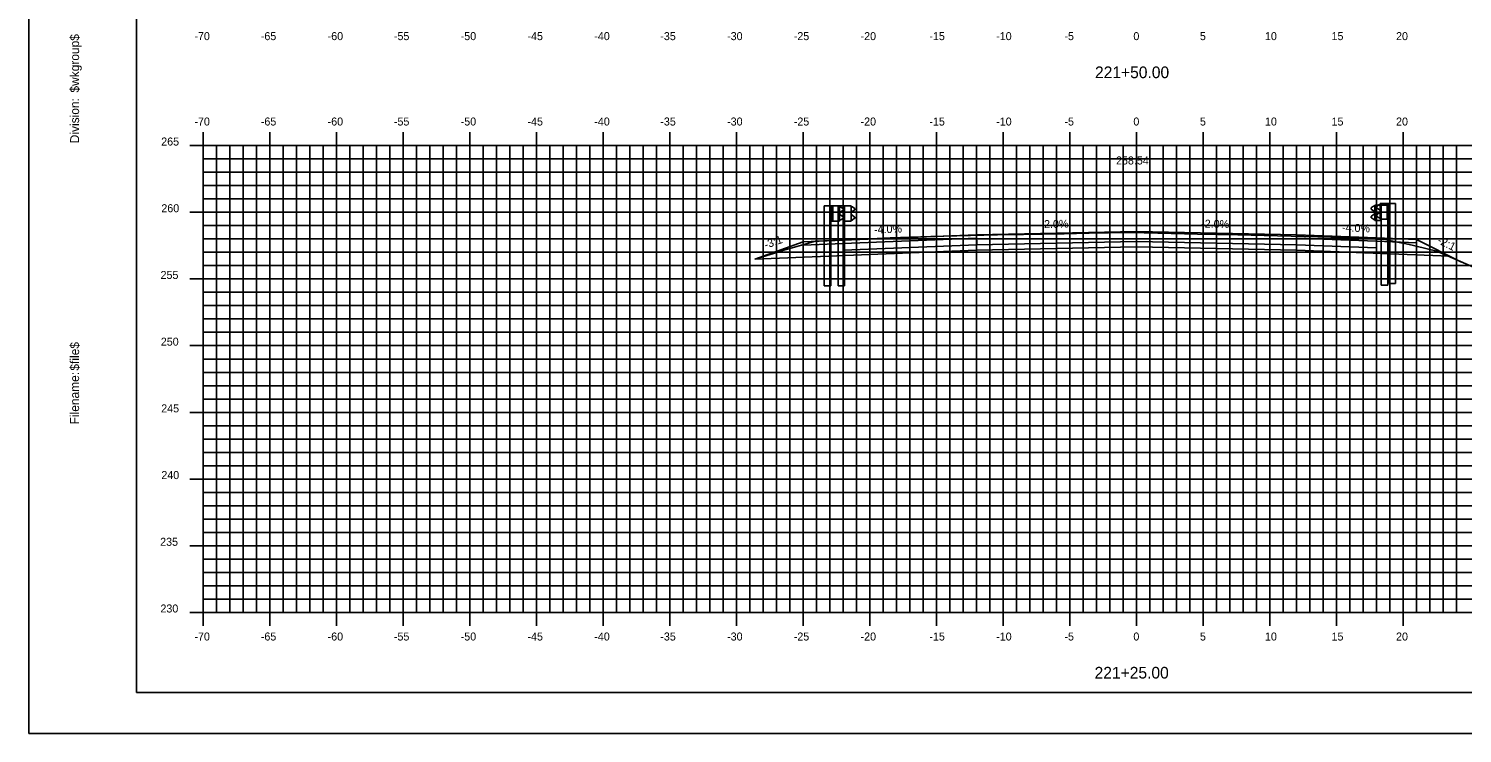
# Model space of a CAD drawing. Extents: x -22 to 1480, y -1511 to 8.
# Drawn here: x 1086.6 to 1194.1, y -184.5 to -131.7 of the extents above; entities that cross this region are included whole.
import ezdxf

# ---------------------------------------------------------------- set-up
doc = ezdxf.new("R2010")
doc.units = 0
for name, color, linetype in [('ANNOTATION', 7, 'Continuous'), ('BORDER', 7, 'Continuous'), ('D_Guardrail_Beam_Lt', 7, 'Continuous'), ('D_Guardrail_Beam_Rt', 7, 'Continuous'), ('D_Roadway_Centerline', 7, 'Continuous'), ('D_Roadway_Centerline_Text', 7, 'Continuous'), ('D_Roadway_Edge_Shoulder', 7, 'Continuous'), ('D_Roadway_Edge_TW', 7, 'Continuous'), ('D_Roadway_SlopeLines', 7, 'Continuous'), ('D_Roadway_SubGrade', 7, 'Continuous'), ('H_V ANNOTATION', 7, 'Continuous'), ('MAJOR', 7, 'Continuous'), ('MINOR', 7, 'Continuous'), ('PLOT BOUNDARY', 7, 'Continuous'), ('S_Guardrail_Beam', 7, 'Continuous'), ('S_Roadway_Centerline', 7, 'Continuous')]:
    doc.layers.add(name, color=color, linetype=linetype)

msp = doc.modelspace()

# ---------------------------------------------------------------- linework, layer by layer
at = {"layer": 'BORDER'}
for p, q in [((1094.72, -76.47), (1094.72, -181.47)), ((1094.72, -181.47), (1254.72, -181.47))]:
    msp.add_line(p, q, dxfattribs=at)
at = {"layer": 'D_Guardrail_Beam_Lt'}
for p, q in [((1187.9, -144.92), (1187.76, -145.02)), ((1187.99, -144.9), (1187.92, -144.92)), ((1187.99, -144.82), (1188.68, -144.82)), ((1187.99, -145.99), (1187.99, -144.82)), ((1188.51, -144.82), (1188.51, -145.99)), ((1188.62, -144.82), (1188.62, -145.99)), ((1188.68, -144.82), (1189.15, -144.82)), ((1188.68, -144.82), (1188.68, -145.99)), ((1189.15, -144.82), (1189.15, -150.82)), ((1187.76, -145.17), (1187.95, -145.3)), ((1187.95, -145.5), (1187.76, -145.64)), ((1187.76, -145.78), (1187.9, -145.88)), ((1187.92, -145.89), (1187.99, -145.9)), ((1187.99, -145.37), (1187.99, -145.44)), ((1188.68, -145.99), (1187.99, -145.99)), ((1188.66, -150.82), (1188.66, -145.99)), ((1188.66, -150.82), (1189.15, -150.82))]:
    msp.add_line(p, q, dxfattribs=at)
for centre, major_axis, start_param, end_param in [((1187.81, -145.09), (-0.0877, 0), 5.323254, 7.243116), ((1187.93, -144.96), (-0.0417, 0), 4.907132, 5.323254), ((1187.81, -145.71), (-0.0877, 0), 5.323254, 7.243116), ((1187.93, -145.85), (-0.0417, 0), 0.959931, 1.376053), ((1187.91, -145.37), (0.0789, 0), 0, 0.959931), ((1187.91, -145.44), (0.0789, 0), 5.323254, 6.283185)]:
    msp.add_ellipse(centre, major_axis=major_axis, ratio=0.995501, start_param=start_param, end_param=end_param, dxfattribs=at)
at = {"layer": 'D_Guardrail_Beam_Rt'}
for p, q in [((1146.29, -144.98), (1146.29, -150.98)), ((1146.76, -144.98), (1146.29, -144.98)), ((1147.45, -144.98), (1146.76, -144.98)), ((1146.76, -144.98), (1146.76, -146.15)), ((1146.83, -144.98), (1146.83, -146.15)), ((1146.93, -144.98), (1146.93, -146.15)), ((1147.45, -146.15), (1147.45, -144.98)), ((1147.45, -145.06), (1147.53, -145.08)), ((1147.54, -145.08), (1147.68, -145.18)), ((1146.76, -146.15), (1147.45, -146.15)), ((1146.78, -150.98), (1146.78, -146.15)), ((1147.53, -146.05), (1147.45, -146.06)), ((1147.46, -145.53), (1147.46, -145.6)), ((1147.68, -145.33), (1147.49, -145.46)), ((1147.49, -145.66), (1147.68, -145.8)), ((1147.68, -145.94), (1147.54, -146.04)), ((1146.78, -150.98), (1146.29, -150.98))]:
    msp.add_line(p, q, dxfattribs=at)
for centre, major_axis, start_param, end_param in [((1147.52, -145.12), (0.0417, 0), 0.959931, 1.376053), ((1147.53, -145.53), (-0.0789, 0), 5.323254, 6.283185), ((1147.53, -145.6), (-0.0789, 0), 6.283185, 7.243116), ((1147.52, -146.01), (0.0417, 0), 4.907132, 5.323254), ((1147.63, -145.25), (0.0877, 0), 5.323254, 7.243116), ((1147.63, -145.87), (0.0877, 0), 5.323254, 7.243116)]:
    msp.add_ellipse(centre, major_axis=major_axis, ratio=0.995501, start_param=start_param, end_param=end_param, dxfattribs=at)
at = {"layer": 'D_Roadway_Centerline'}
msp.add_lwpolyline([(1141.09, -148.98), (1144.72, -147.68), (1147.72, -147.56), (1157.72, -147.16), (1169.72, -146.92), (1181.72, -147.16), (1187.72, -147.4), (1190.72, -147.52), (1194.09, -149.21)], dxfattribs=at)
at = {"layer": 'D_Roadway_Edge_Shoulder'}
for points in [[(1157.72, -147.16), (1147.72, -147.56), (1147.72, -147.56), (1144.72, -147.68), (1144.72, -147.93), (1147.72, -147.81), (1147.72, -147.81), (1157.72, -147.41)], [(1157.72, -147.16), (1147.72, -147.56), (1147.72, -147.56), (1144.72, -147.68), (1144.72, -147.93), (1147.72, -147.81), (1147.72, -147.81), (1147.73, -148.31), (1157.73, -147.91)], [(1181.72, -147.16), (1187.72, -147.4), (1187.72, -147.4), (1190.72, -147.52), (1190.72, -147.77), (1187.72, -147.65), (1187.72, -147.65), (1187.71, -148.15), (1181.71, -147.91)], [(1181.72, -147.16), (1187.72, -147.4), (1187.72, -147.4), (1190.72, -147.52), (1190.72, -147.77), (1187.72, -147.65), (1187.72, -147.65), (1181.72, -147.41)]]:
    msp.add_lwpolyline(points, close=True, dxfattribs=at)
at = {"layer": 'D_Roadway_Edge_TW'}
msp.add_lwpolyline([(1181.72, -147.91), (1181.72, -147.16), (1169.72, -146.92), (1157.72, -147.16), (1157.72, -147.91), (1169.72, -147.67)], close=True, dxfattribs=at)
at = {"layer": 'D_Roadway_SlopeLines'}
for points in [[(1144.72, -147.68), (1141.09, -148.98)], [(1190.72, -147.52), (1194.09, -149.21)]]:
    msp.add_lwpolyline(points, dxfattribs=at)
at = {"layer": 'D_Roadway_SubGrade'}
for p, q in [((1157.72, -148.31), (1141.09, -148.98)), ((1181.72, -148.31), (1193.22, -148.77))]:
    msp.add_line(p, q, dxfattribs=at)
msp.add_lwpolyline([(1181.72, -148.31), (1181.72, -147.91), (1169.72, -147.67), (1157.72, -147.91), (1157.72, -148.31), (1169.72, -148.07)], close=True, dxfattribs=at)
at = {"layer": 'MAJOR'}
for p, q in [((1099.72, -139.46), (1099.72, -140.47)), ((1104.72, -139.46), (1104.72, -140.47)), ((1109.72, -139.46), (1109.72, -140.47)), ((1114.72, -139.46), (1114.72, -140.47)), ((1119.72, -139.46), (1119.72, -140.47)), ((1124.72, -139.46), (1124.72, -140.47)), ((1129.72, -139.46), (1129.72, -140.47)), ((1134.72, -139.46), (1134.72, -140.47)), ((1139.72, -139.46), (1139.72, -140.47)), ((1144.72, -139.46), (1144.72, -140.47)), ((1149.72, -139.46), (1149.72, -140.47)), ((1154.72, -139.46), (1154.72, -140.47)), ((1159.72, -139.46), (1159.72, -140.47)), ((1164.72, -139.46), (1164.72, -140.47)), ((1169.72, -139.46), (1169.72, -140.47)), ((1174.72, -139.46), (1174.72, -140.47)), ((1179.72, -139.46), (1179.72, -140.47)), ((1184.72, -139.46), (1184.72, -140.47)), ((1189.72, -139.46), (1189.72, -140.47)), ((1098.72, -140.47), (1099.72, -140.47)), ((1099.72, -140.47), (1239.72, -140.47)), ((1099.72, -175.47), (1099.72, -140.47)), ((1099.72, -175.47), (1099.72, -140.47)), ((1099.72, -140.47), (1239.72, -140.47)), ((1104.72, -175.47), (1104.72, -140.47)), ((1109.72, -175.47), (1109.72, -140.47)), ((1114.72, -175.47), (1114.72, -140.47)), ((1119.72, -175.47), (1119.72, -140.47)), ((1124.72, -175.47), (1124.72, -140.47)), ((1129.72, -175.47), (1129.72, -140.47)), ((1134.72, -175.47), (1134.72, -140.47)), ((1139.72, -175.47), (1139.72, -140.47)), ((1144.72, -175.47), (1144.72, -140.47)), ((1149.72, -175.47), (1149.72, -140.47)), ((1154.72, -175.47), (1154.72, -140.47)), ((1159.72, -175.47), (1159.72, -140.47)), ((1164.72, -175.47), (1164.72, -140.47)), ((1169.72, -175.47), (1169.72, -140.47)), ((1174.72, -175.47), (1174.72, -140.47)), ((1179.72, -175.47), (1179.72, -140.47)), ((1184.72, -175.47), (1184.72, -140.47)), ((1189.72, -175.47), (1189.72, -140.47)), ((1098.72, -145.47), (1099.72, -145.47)), ((1099.72, -145.47), (1239.72, -145.47)), ((1098.72, -150.47), (1099.72, -150.47)), ((1099.72, -150.47), (1239.72, -150.47)), ((1098.72, -155.47), (1099.72, -155.47)), ((1099.72, -155.47), (1239.72, -155.47)), ((1098.72, -160.47), (1099.72, -160.47)), ((1099.72, -160.47), (1239.72, -160.47)), ((1098.72, -165.47), (1099.72, -165.47)), ((1099.72, -165.47), (1239.72, -165.47)), ((1098.72, -170.47), (1099.72, -170.47)), ((1099.72, -170.47), (1239.72, -170.47)), ((1098.72, -175.47), (1099.72, -175.47)), ((1099.72, -175.47), (1239.72, -175.47)), ((1099.72, -175.47), (1239.72, -175.47)), ((1099.72, -176.47), (1099.72, -175.47)), ((1104.72, -176.47), (1104.72, -175.47)), ((1109.72, -176.47), (1109.72, -175.47)), ((1114.72, -176.47), (1114.72, -175.47)), ((1119.72, -176.47), (1119.72, -175.47)), ((1124.72, -176.47), (1124.72, -175.47)), ((1129.72, -176.47), (1129.72, -175.47)), ((1134.72, -176.47), (1134.72, -175.47)), ((1139.72, -176.47), (1139.72, -175.47)), ((1144.72, -176.47), (1144.72, -175.47)), ((1149.72, -176.47), (1149.72, -175.47)), ((1154.72, -176.47), (1154.72, -175.47)), ((1159.72, -176.47), (1159.72, -175.47)), ((1164.72, -176.47), (1164.72, -175.47)), ((1169.72, -176.47), (1169.72, -175.47)), ((1174.72, -176.47), (1174.72, -175.47)), ((1179.72, -176.47), (1179.72, -175.47)), ((1184.72, -176.47), (1184.72, -175.47)), ((1189.72, -176.47), (1189.72, -175.47))]:
    msp.add_line(p, q, dxfattribs=at)
at = {"layer": 'MINOR'}
for p, q in [((1100.72, -175.47), (1100.72, -140.47)), ((1101.72, -175.47), (1101.72, -140.47)), ((1102.72, -175.47), (1102.72, -140.47)), ((1103.72, -175.47), (1103.72, -140.47)), ((1105.72, -175.47), (1105.72, -140.47)), ((1106.72, -175.47), (1106.72, -140.47)), ((1107.72, -175.47), (1107.72, -140.47)), ((1108.72, -175.47), (1108.72, -140.47)), ((1110.72, -175.47), (1110.72, -140.47)), ((1111.72, -175.47), (1111.72, -140.47)), ((1112.72, -175.47), (1112.72, -140.47)), ((1113.72, -175.47), (1113.72, -140.47)), ((1115.72, -175.47), (1115.72, -140.47)), ((1116.72, -175.47), (1116.72, -140.47)), ((1117.72, -175.47), (1117.72, -140.47)), ((1118.72, -175.47), (1118.72, -140.47)), ((1120.72, -175.47), (1120.72, -140.47)), ((1121.72, -175.47), (1121.72, -140.47)), ((1122.72, -175.47), (1122.72, -140.47)), ((1123.72, -175.47), (1123.72, -140.47)), ((1125.72, -175.47), (1125.72, -140.47)), ((1126.72, -175.47), (1126.72, -140.47)), ((1127.72, -175.47), (1127.72, -140.47)), ((1128.72, -175.47), (1128.72, -140.47)), ((1130.72, -175.47), (1130.72, -140.47)), ((1131.72, -175.47), (1131.72, -140.47)), ((1132.72, -175.47), (1132.72, -140.47)), ((1133.72, -175.47), (1133.72, -140.47)), ((1135.72, -175.47), (1135.72, -140.47)), ((1136.72, -175.47), (1136.72, -140.47)), ((1137.72, -175.47), (1137.72, -140.47)), ((1138.72, -175.47), (1138.72, -140.47)), ((1140.72, -175.47), (1140.72, -140.47)), ((1141.72, -175.47), (1141.72, -140.47)), ((1142.72, -175.47), (1142.72, -140.47)), ((1143.72, -175.47), (1143.72, -140.47)), ((1145.72, -175.47), (1145.72, -140.47)), ((1146.72, -175.47), (1146.72, -140.47)), ((1147.72, -175.47), (1147.72, -140.47)), ((1148.72, -175.47), (1148.72, -140.47)), ((1150.72, -175.47), (1150.72, -140.47)), ((1151.72, -175.47), (1151.72, -140.47)), ((1152.72, -175.47), (1152.72, -140.47)), ((1153.72, -175.47), (1153.72, -140.47)), ((1155.72, -175.47), (1155.72, -140.47)), ((1156.72, -175.47), (1156.72, -140.47)), ((1157.72, -175.47), (1157.72, -140.47)), ((1158.72, -175.47), (1158.72, -140.47)), ((1160.72, -175.47), (1160.72, -140.47)), ((1161.72, -175.47), (1161.72, -140.47)), ((1162.72, -175.47), (1162.72, -140.47)), ((1163.72, -175.47), (1163.72, -140.47)), ((1165.72, -175.47), (1165.72, -140.47)), ((1166.72, -175.47), (1166.72, -140.47)), ((1167.72, -175.47), (1167.72, -140.47)), ((1168.72, -175.47), (1168.72, -140.47)), ((1170.72, -175.47), (1170.72, -140.47)), ((1171.72, -175.47), (1171.72, -140.47)), ((1172.72, -175.47), (1172.72, -140.47)), ((1173.72, -175.47), (1173.72, -140.47)), ((1175.72, -175.47), (1175.72, -140.47)), ((1176.72, -175.47), (1176.72, -140.47)), ((1177.72, -175.47), (1177.72, -140.47)), ((1178.72, -175.47), (1178.72, -140.47)), ((1180.72, -175.47), (1180.72, -140.47)), ((1181.72, -175.47), (1181.72, -140.47)), ((1182.72, -175.47), (1182.72, -140.47)), ((1183.72, -175.47), (1183.72, -140.47)), ((1185.72, -175.47), (1185.72, -140.47)), ((1186.72, -175.47), (1186.72, -140.47)), ((1187.72, -175.47), (1187.72, -140.47)), ((1188.72, -175.47), (1188.72, -140.47)), ((1190.72, -175.47), (1190.72, -140.47)), ((1191.72, -175.47), (1191.72, -140.47)), ((1192.72, -175.47), (1192.72, -140.47)), ((1193.72, -175.47), (1193.72, -140.47)), ((1099.72, -141.47), (1239.72, -141.47)), ((1099.72, -141.47), (1100.72, -141.47)), ((1099.72, -142.47), (1239.72, -142.47)), ((1099.72, -142.47), (1100.72, -142.47)), ((1099.72, -143.47), (1239.72, -143.47)), ((1099.72, -143.47), (1100.72, -143.47)), ((1099.72, -144.47), (1239.72, -144.47)), ((1099.72, -144.47), (1100.72, -144.47)), ((1099.72, -146.47), (1239.72, -146.47)), ((1099.72, -146.47), (1100.72, -146.47)), ((1099.72, -147.47), (1239.72, -147.47)), ((1099.72, -147.47), (1100.72, -147.47)), ((1099.72, -148.47), (1239.72, -148.47)), ((1099.72, -148.47), (1100.72, -148.47)), ((1099.72, -149.47), (1239.72, -149.47)), ((1099.72, -149.47), (1100.72, -149.47)), ((1099.72, -151.47), (1239.72, -151.47)), ((1099.72, -151.47), (1100.72, -151.47)), ((1099.72, -152.47), (1239.72, -152.47)), ((1099.72, -152.47), (1100.72, -152.47)), ((1099.72, -153.47), (1239.72, -153.47)), ((1099.72, -153.47), (1100.72, -153.47)), ((1099.72, -154.47), (1239.72, -154.47)), ((1099.72, -154.47), (1100.72, -154.47)), ((1099.72, -156.47), (1239.72, -156.47)), ((1099.72, -156.47), (1100.72, -156.47)), ((1099.72, -157.47), (1239.72, -157.47)), ((1099.72, -157.47), (1100.72, -157.47)), ((1099.72, -158.47), (1239.72, -158.47)), ((1099.72, -158.47), (1100.72, -158.47)), ((1099.72, -159.47), (1239.72, -159.47)), ((1099.72, -159.47), (1100.72, -159.47)), ((1099.72, -161.47), (1239.72, -161.47)), ((1099.72, -161.47), (1100.72, -161.47)), ((1099.72, -162.47), (1239.72, -162.47)), ((1099.72, -162.47), (1100.72, -162.47)), ((1099.72, -163.47), (1239.72, -163.47)), ((1099.72, -163.47), (1100.72, -163.47)), ((1099.72, -164.47), (1239.72, -164.47)), ((1099.72, -164.47), (1100.72, -164.47)), ((1099.72, -166.47), (1239.72, -166.47)), ((1099.72, -166.47), (1100.72, -166.47)), ((1099.72, -167.47), (1239.72, -167.47)), ((1099.72, -167.47), (1100.72, -167.47)), ((1099.72, -168.47), (1239.72, -168.47)), ((1099.72, -168.47), (1100.72, -168.47)), ((1099.72, -169.47), (1239.72, -169.47)), ((1099.72, -169.47), (1100.72, -169.47)), ((1099.72, -171.47), (1239.72, -171.47)), ((1099.72, -171.47), (1100.72, -171.47)), ((1099.72, -172.47), (1239.72, -172.47)), ((1099.72, -172.47), (1100.72, -172.47)), ((1099.72, -173.47), (1239.72, -173.47)), ((1099.72, -173.47), (1100.72, -173.47)), ((1099.72, -174.47), (1239.72, -174.47)), ((1099.72, -174.47), (1100.72, -174.47))]:
    msp.add_line(p, q, dxfattribs=at)
at = {"layer": 'PLOT BOUNDARY'}
msp.add_lwpolyline([(1086.63, -184.53), (1256.63, -184.53), (1256.63, -74.53), (1086.63, -74.53)], close=True, dxfattribs=at)
at = {"layer": 'S_Guardrail_Beam'}
for p, q in [((1147.33, -144.98), (1147.33, -150.98)), ((1147.82, -144.98), (1147.33, -144.98)), ((1148.31, -144.98), (1147.82, -144.98)), ((1147.82, -144.98), (1147.82, -146.14)), ((1148.31, -146.14), (1148.31, -144.98)), ((1148.31, -145.05), (1148.39, -145.06)), ((1148.41, -145.07), (1148.55, -145.17)), ((1187.48, -145.02), (1187.34, -145.12)), ((1187.58, -145), (1187.5, -145.01)), ((1187.58, -144.93), (1188.07, -144.93)), ((1187.58, -146.09), (1187.58, -144.93)), ((1188.07, -144.93), (1188.56, -144.93)), ((1188.07, -144.93), (1188.07, -146.09)), ((1188.56, -144.93), (1188.56, -150.93)), ((1147.82, -150.98), (1147.82, -146.14)), ((1147.82, -146.14), (1148.31, -146.14)), ((1148.39, -146.06), (1148.31, -146.07)), ((1148.32, -145.51), (1148.32, -145.61)), ((1148.55, -145.31), (1148.36, -145.45)), ((1148.36, -145.67), (1148.55, -145.81)), ((1148.55, -145.95), (1148.41, -146.05)), ((1187.34, -145.26), (1187.53, -145.4)), ((1187.53, -145.62), (1187.34, -145.76)), ((1187.34, -145.9), (1187.48, -146)), ((1187.5, -146.01), (1187.58, -146.02)), ((1187.57, -145.46), (1187.57, -145.56)), ((1188.07, -146.09), (1187.58, -146.09)), ((1188.07, -150.93), (1188.07, -146.09)), ((1147.82, -150.98), (1147.33, -150.98)), ((1188.07, -150.93), (1188.56, -150.93))]:
    msp.add_line(p, q, dxfattribs=at)
for centre, major_axis, start_param, end_param in [((1148.38, -145.11), (0.0417, 0), 0.959931, 1.396263), ((1187.39, -145.19), (-0.0877, 0), 5.323254, 7.243116), ((1187.51, -145.06), (-0.0417, 0), 4.886922, 5.323254), ((1148.4, -145.51), (-0.0789, 0), 5.323254, 6.283185), ((1148.4, -145.61), (-0.0789, 0), 6.283185, 7.243116), ((1148.38, -146.02), (0.0417, 0), 4.886922, 5.323254), ((1148.5, -145.24), (0.0877, 0), 5.323254, 7.243116), ((1148.5, -145.88), (0.0877, 0), 5.323254, 7.243116), ((1187.39, -145.83), (-0.0877, 0), 5.323254, 7.243116), ((1187.51, -145.97), (-0.0417, 0), 0.959931, 1.396263), ((1187.49, -145.46), (0.0789, 0), 0, 0.959931), ((1187.49, -145.56), (0.0789, 0), 5.323254, 6.283185)]:
    msp.add_ellipse(centre, major_axis=major_axis, ratio=0.995501, start_param=start_param, end_param=end_param, dxfattribs=at)
at = {"layer": 'S_Roadway_Centerline'}
msp.add_lwpolyline([(1141.09, -148.98), (1142.25, -148.63), (1143.06, -148.38), (1143.17, -148.35), (1143.53, -148.24), (1145.63, -147.64), (1146.31, -147.61), (1149.3, -147.48), (1151.23, -147.4), (1154.3, -147.28), (1156.24, -147.24), (1159.3, -147.17), (1161.25, -147.13), (1164.3, -147.08), (1166.17, -147.05), (1169.1, -147), (1169.19, -147), (1169.3, -147), (1172.32, -147.07), (1174.3, -147.11), (1177.32, -147.17), (1179.3, -147.21), (1182.31, -147.3), (1184.3, -147.35), (1187.64, -147.49), (1188.39, -147.52), (1188.57, -147.56), (1189.54, -147.76), (1189.95, -147.85), (1190.49, -147.97), (1190.68, -148.01), (1192.23, -148.39), (1230.29, -164.99)], dxfattribs=at)

# ---------------------------------------------------------------- texts
at = {"layer": 'ANNOTATION'}
for s, rotation, p in [('-2.0%', 1.1458, (1162.52, -146.67)), ('-2.0%', 358.8542, (1174.56, -146.62)), ('-3:1', 19.6413, (1141.91, -148.22)), ('-4.0%', 2.2906, (1150.04, -147.07)), ('-4.0%', 357.7094, (1185.12, -146.9)), ('-2:1', 333.4349, (1192.23, -147.76))]:
    msp.add_text(s, height=0.6, rotation=rotation, dxfattribs=at).set_placement(p)
at = {"layer": 'BORDER'}
for s, p in [('$wkgroup$', (1090.41, -136.5)), ('Division:', (1090.41, -140.3)), ('$file$', (1090.41, -157.34)), ('Filename:', (1090.41, -161.37))]:
    msp.add_text(s, height=0.67, rotation=90, dxfattribs=at).set_placement(p)
at = {"layer": 'D_Roadway_Centerline'}
for s, p in [('C', (1169.72, -146.92)), ('L', (1169.72, -146.93))]:
    msp.add_text(s, height=0.0146, dxfattribs=at).set_placement(p)
at = {"layer": 'D_Roadway_Centerline_Text'}
msp.add_text('258.54', height=0.6, dxfattribs=at).set_placement((1168.18, -141.89))
at = {"layer": 'H_V ANNOTATION'}
for s, height, p in [('-70', 0.6, (1099.06, -132.57)), ('-65', 0.6, (1104.04, -132.57)), ('-60', 0.6, (1109.05, -132.57)), ('-55', 0.6, (1114.02, -132.57)), ('-50', 0.6, (1119.03, -132.57)), ('-45', 0.6, (1124.04, -132.57)), ('-40', 0.6, (1129.05, -132.57)), ('-35', 0.6, (1134, -132.57)), ('-30', 0.6, (1139.01, -132.57)), ('-25', 0.6, (1144.01, -132.57)), ('-20', 0.6, (1149.02, -132.57)), ('-15', 0.6, (1154.18, -132.57)), ('-10', 0.6, (1159.19, -132.57)), ('-5', 0.6, (1164.31, -132.57)), ('0', 0.6, (1169.48, -132.57)), ('5', 0.6, (1174.47, -132.57)), ('10', 0.6, (1179.35, -132.57)), ('15', 0.6, (1184.34, -132.57)), ('20', 0.6, (1189.18, -132.57)), ('221+50.00', 0.875, (1166.6, -135.42)), ('-70', 0.6, (1099.06, -138.97)), ('-65', 0.6, (1104.04, -138.97)), ('-60', 0.6, (1109.05, -138.97)), ('-55', 0.6, (1114.02, -138.97)), ('-50', 0.6, (1119.03, -138.97)), ('-45', 0.6, (1124.04, -138.97)), ('-40', 0.6, (1129.05, -138.97)), ('-35', 0.6, (1134, -138.97)), ('-30', 0.6, (1139.01, -138.97)), ('-25', 0.6, (1144.01, -138.97)), ('-20', 0.6, (1149.02, -138.97)), ('-15', 0.6, (1154.18, -138.97)), ('-10', 0.6, (1159.19, -138.97)), ('-5', 0.6, (1164.31, -138.97)), ('0', 0.6, (1169.48, -138.97)), ('5', 0.6, (1174.47, -138.97)), ('10', 0.6, (1179.35, -138.97)), ('15', 0.6, (1184.34, -138.97)), ('20', 0.6, (1189.18, -138.97)), ('265', 0.6, (1096.57, -140.47)), ('260', 0.6, (1096.58, -145.47)), ('255', 0.6, (1096.52, -150.47)), ('250', 0.6, (1096.54, -155.47)), ('245', 0.6, (1096.57, -160.47)), ('240', 0.6, (1096.58, -165.47)), ('235', 0.6, (1096.49, -170.47)), ('230', 0.6, (1096.51, -175.47)), ('-70', 0.6, (1099.06, -177.57)), ('-65', 0.6, (1104.04, -177.57)), ('-60', 0.6, (1109.05, -177.57)), ('-55', 0.6, (1114.02, -177.57)), ('-50', 0.6, (1119.03, -177.57)), ('-45', 0.6, (1124.04, -177.57)), ('-40', 0.6, (1129.05, -177.57)), ('-35', 0.6, (1134, -177.57)), ('-30', 0.6, (1139.01, -177.57)), ('-25', 0.6, (1144.01, -177.57)), ('-20', 0.6, (1149.02, -177.57)), ('-15', 0.6, (1154.18, -177.57)), ('-10', 0.6, (1159.19, -177.57)), ('-5', 0.6, (1164.31, -177.57)), ('0', 0.6, (1169.48, -177.57)), ('5', 0.6, (1174.47, -177.57)), ('10', 0.6, (1179.35, -177.57)), ('15', 0.6, (1184.34, -177.57)), ('20', 0.6, (1189.18, -177.57)), ('221+25.00', 0.875, (1166.57, -180.42))]:
    msp.add_text(s, height=height, dxfattribs=at).set_placement(p)

doc.saveas('drawing.dxf')
